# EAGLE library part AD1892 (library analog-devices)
Integrated Digital Receiver/Rate Converter Auto generated by make-symbol-device-package-bsdl.ulp Rev. 33 Source: http://www.analog.com/static/imported-files/data_sheets/AD1892.pdf
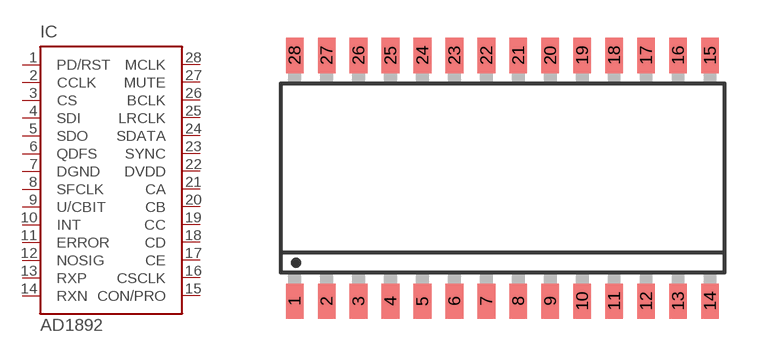
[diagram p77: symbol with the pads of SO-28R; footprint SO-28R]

Designator prefix IC

## AD1892 (OC_FARNELL: unknown; OC_NEWARK: unknown)  [SO-28R]
1  PD/RST  in
2  CCLK  in
3  CS  in
4  SDI  in
5  SDO  out
6  QDFS  out
7  DGND  pwr
8  SFCLK  out
9  U/CBIT  out
10  INT  out
11  ERROR  out
12  NOSIG  out
13  RXP  in
14  RXN  in
15  CON/PRO  out
16  CSCLK  out
17  CE  out
18  CD  out
19  CC  out
20  CB  out
21  CA  out
22  DVDD  pwr
23  SYNC  in
24  SDATA  out
25  LRCLK  out
26  BCLK  out
27  MUTE  in
28  MCLK  in

## Footprint SO-28R (pad centres in mm)
R-28 (S-Suffix) 28-Lead Wide-Body SO SOL-28 Source: http://www.analog.com/static/imported-files/data_sheets/AD1877.pdf
smd 0.7 x 1.4: 1 -8.255,-4.88; 2 -6.985,-4.88; 3 -5.715,-4.88; 4 -4.445,-4.88; 5 -3.175,-4.88; 6 -1.905,-4.88; 7 -0.635,-4.88; 8 0.635,-4.88; 9 1.905,-4.88; 10 3.175,-4.88; 11 4.445,-4.88; 12 5.715,-4.88; 13 6.985,-4.88; 14 8.255,-4.88; 15 8.255,4.88; 16 6.985,4.88; 17 5.715,4.88; 18 4.445,4.88; 19 3.175,4.88; 20 1.905,4.88; 21 0.635,4.88; 22 -0.635,4.88; 23 -1.905,4.88; 24 -3.175,4.88; 25 -4.445,4.88; 26 -5.715,4.88; 27 -6.985,4.88; 28 -8.255,4.88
